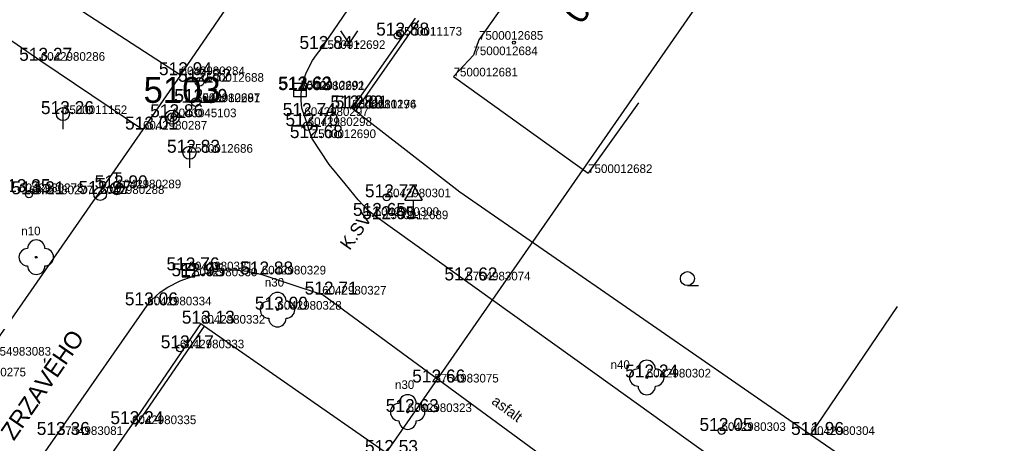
# Model space of a CAD drawing. Extents: x -669251 to -668549, y -1128351 to -1127698.
# Drawn here: x -668939.6 to -668883.4, y -1128097.2 to -1128072.7 of the extents above; entities that cross this region are included whole.
import ezdxf

# ---------------------------------------------------------------- set-up
doc = ezdxf.new("R2010")
doc.units = 0
for name, color, linetype in [('Vrstva 1', 7, 'Continuous'), ('Vrstva 10', 7, 'Continuous'), ('Vrstva 2', 7, 'Continuous'), ('Vrstva 22', 7, 'Continuous'), ('Vrstva 25', 7, 'Continuous'), ('Vrstva 27', 7, 'Continuous'), ('Vrstva 28', 7, 'Continuous'), ('Vrstva 3', 7, 'Continuous'), ('Vrstva 34', 7, 'Continuous'), ('Vrstva 36', 7, 'Continuous'), ('Vrstva 40', 7, 'Continuous'), ('Vrstva 42', 7, 'Continuous'), ('Vrstva 44', 7, 'Continuous'), ('Vrstva 45', 7, 'Continuous'), ('Vrstva 47', 7, 'Continuous'), ('Vrstva 5', 7, 'Continuous'), ('Vrstva 58', 7, 'Continuous'), ('Vrstva 6', 7, 'Continuous'), ('Vrstva 60', 7, 'Continuous'), ('Vrstva 63', 7, 'Continuous'), ('Vrstva 7', 7, 'Continuous'), ('Vrstva 8', 7, 'Continuous')]:
    doc.layers.add(name, color=color, linetype=linetype)

msp = doc.modelspace()

# ---------------------------------------------------------------- linework, layer by layer
at = {"layer": 'Vrstva 1'}
for p, q in [((-668917.686, -1128073.591), (-668917.686, -1128073.591)), ((-668922.122, -1128074.364), (-668922.122, -1128074.364)), ((-668912.989, -1128073.832), (-668912.989, -1128073.832)), ((-668913.309, -1128074.724), (-668913.309, -1128074.724)), ((-668938.339, -1128075.049), (-668938.339, -1128075.049)), ((-668930.251, -1128075.881), (-668930.251, -1128075.881)), ((-668914.458, -1128075.953), (-668914.458, -1128075.953)), ((-668929.15, -1128076.263), (-668929.15, -1128076.263)), ((-668923.347, -1128076.747), (-668923.347, -1128076.747)), ((-668923.31, -1128076.708), (-668923.31, -1128076.708)), ((-668929.366, -1128077.444), (-668929.366, -1128077.444)), ((-668929.36, -1128077.427), (-668929.36, -1128077.427)), ((-668937.059, -1128078.133), (-668937.059, -1128078.133)), ((-668923.09, -1128078.24), (-668923.09, -1128078.24)), ((-668920.329, -1128077.805), (-668920.329, -1128077.805)), ((-668920.315, -1128077.808), (-668920.315, -1128077.808)), ((-668930.737, -1128078.313), (-668930.737, -1128078.313)), ((-668922.897, -1128078.823), (-668922.897, -1128078.823)), ((-668932.431, -1128079.028), (-668932.431, -1128079.028)), ((-668922.664, -1128079.521), (-668922.664, -1128079.521)), ((-668929.788, -1128080.369), (-668929.788, -1128080.369)), ((-668906.673, -1128081.541), (-668906.673, -1128081.541)), ((-668939.025, -1128082.769), (-668939.025, -1128082.769)), ((-668934.906, -1128082.752), (-668934.906, -1128082.752)), ((-668933.936, -1128082.425), (-668933.936, -1128082.425)), ((-668918.335, -1128082.945), (-668918.335, -1128082.945)), ((-668919.017, -1128084.023), (-668919.017, -1128084.023)), ((-668918.483, -1128084.212), (-668918.483, -1128084.212)), ((-668929.795, -1128087.171), (-668929.795, -1128087.171)), ((-668929.527, -1128087.514), (-668929.527, -1128087.514)), ((-668925.555, -1128087.41), (-668925.555, -1128087.41)), ((-668913.722, -1128087.754), (-668913.722, -1128087.754)), ((-668922.059, -1128088.573), (-668922.059, -1128088.573)), ((-668932.181, -1128089.197), (-668932.181, -1128089.197)), ((-668924.648, -1128089.447), (-668924.648, -1128089.447)), ((-668929.072, -1128090.256), (-668929.072, -1128090.256)), ((-668930.29, -1128091.683), (-668930.29, -1128091.683)), ((-668903.282, -1128093.37), (-668903.282, -1128093.37)), ((-668915.564, -1128093.66), (-668915.564, -1128093.66)), ((-668917.116, -1128095.37), (-668917.116, -1128095.37)), ((-668933.061, -1128096.069), (-668933.061, -1128096.069)), ((-668937.301, -1128096.694), (-668937.301, -1128096.694)), ((-668898.955, -1128096.464), (-668898.955, -1128096.464)), ((-668893.8, -1128096.695), (-668893.8, -1128096.695))]:
    msp.add_line(p, q, dxfattribs=at)
at = {"layer": 'Vrstva 10'}
for p, q in [((-668930.251, -1128075.881), (-668923.264, -1128065.653)), ((-668945.235, -1128070.371), (-668938.339, -1128075.049)), ((-668930.251, -1128075.881), (-668936.233, -1128072.009)), ((-668938.339, -1128075.049), (-668932.431, -1128079.028)), ((-668930.251, -1128075.881), (-668932.431, -1128079.028)), ((-668932.431, -1128079.028), (-668946.986, -1128099.95)), ((-668899.916, -1128104.805), (-668922.059, -1128088.573))]:
    msp.add_line(p, q, dxfattribs=at)
for points in [[(-668891.508, -1128103.738), (-668905.262, -1128093.88), (-668919.017, -1128084.023), (-668919.397, -1128083.714), (-668919.979, -1128083.09), (-668920.732, -1128082.168), (-668921.655, -1128081.051), (-668922.664, -1128079.521), (-668923.09, -1128078.24), (-668923.232, -1128077.783), (-668923.284, -1128077.351), (-668923.278, -1128076.957), (-668923.161, -1128076.255), (-668922.993, -1128075.739), (-668922.626, -1128075.026), (-668922.397, -1128074.711), (-668922.122, -1128074.364), (-668919.566, -1128070.623)], [(-668949.552, -1128114.045), (-668940.866, -1128101.621), (-668932.181, -1128089.197), (-668931.937, -1128088.891), (-668931.427, -1128088.43), (-668930.99, -1128088.14), (-668930.277, -1128087.786), (-668929.527, -1128087.514), (-668928.538, -1128087.269), (-668927.781, -1128087.169), (-668927.212, -1128087.149), (-668926.37, -1128087.215), (-668925.555, -1128087.41), (-668923.807, -1128087.992), (-668922.059, -1128088.573)]]:
    msp.add_lwpolyline(points, dxfattribs=at)
at = {"layer": 'Vrstva 22'}
for centre in [(-668938.603, -1128086.412), (-668924.648, -1128089.447), (-668903.282, -1128093.37), (-668917.116, -1128095.37)]:
    msp.add_circle(centre, 0.05, dxfattribs=at)
for centre, start, end in [((-668938.603, -1128085.912), 0, 180), ((-668939.103, -1128086.412), 90, 270), ((-668938.103, -1128086.412), 270, 90), ((-668938.603, -1128086.912), 180, 0), ((-668925.148, -1128089.447), 90, 270), ((-668924.648, -1128088.947), 0, 180), ((-668924.148, -1128089.447), 270, 90), ((-668924.648, -1128089.947), 180, 0), ((-668903.782, -1128093.37), 90, 270), ((-668903.282, -1128092.87), 0, 180), ((-668902.782, -1128093.37), 270, 90), ((-668903.282, -1128093.87), 180, 0), ((-668917.116, -1128094.87), 0, 180), ((-668917.616, -1128095.37), 90, 270), ((-668916.616, -1128095.37), 270, 90), ((-668917.116, -1128095.87), 180, 0)]:
    msp.add_arc(centre, 0.5, start, end, dxfattribs=at)
at = {"layer": 'Vrstva 25'}
for centre in [(-668917.686, -1128073.591), (-668917.562, -1128073.461), (-668939.025, -1128082.769), (-668918.335, -1128082.945), (-668930.29, -1128091.683), (-668898.955, -1128096.464)]:
    msp.add_circle(centre, 0.2, dxfattribs=at)
at = {"layer": 'Vrstva 27'}
for p, q in [((-668923.722, -1128076.747), (-668922.972, -1128076.747)), ((-668937.059, -1128077.758), (-668937.059, -1128079.008)), ((-668929.738, -1128079.996), (-668929.738, -1128081.246)), ((-668930.17, -1128087.171), (-668929.42, -1128087.171))]:
    msp.add_line(p, q, dxfattribs=at)
for points in [[(-668923.722, -1128077.121), (-668922.972, -1128077.121), (-668922.972, -1128076.371), (-668923.722, -1128076.371)], [(-668930.17, -1128087.545), (-668929.42, -1128087.545), (-668929.42, -1128086.795), (-668930.17, -1128086.795)]]:
    msp.add_lwpolyline(points, close=True, dxfattribs=at)
for centre in [(-668937.059, -1128078.133), (-668929.738, -1128080.371)]:
    msp.add_circle(centre, 0.375, dxfattribs=at)
at = {"layer": 'Vrstva 28'}
for p, q in [((-668929.4, -1128076.263), (-668929.9, -1128076.263)), ((-668928.9, -1128076.263), (-668928.4, -1128076.263)), ((-668929.616, -1128077.444), (-668930.116, -1128077.444)), ((-668929.116, -1128077.444), (-668928.616, -1128077.444)), ((-668930.99, -1128078.31), (-668931.49, -1128078.31)), ((-668930.49, -1128078.31), (-668929.99, -1128078.31)), ((-668923.147, -1128078.823), (-668923.647, -1128078.823)), ((-668922.647, -1128078.823), (-668922.147, -1128078.823)), ((-668934.186, -1128081.525), (-668933.686, -1128081.525)), ((-668933.936, -1128082.05), (-668933.936, -1128081.525)), ((-668935.156, -1128081.852), (-668934.656, -1128081.852)), ((-668934.906, -1128082.377), (-668934.906, -1128081.852)), ((-668934.201, -1128082.69), (-668933.671, -1128082.16)), ((-668935.171, -1128083.017), (-668934.641, -1128082.487))]:
    msp.add_line(p, q, dxfattribs=at)
for centre, radius in [((-668929.15, -1128076.263), 0.25), ((-668929.366, -1128077.444), 0.25), ((-668930.74, -1128078.31), 0.25), ((-668922.897, -1128078.823), 0.25), ((-668933.936, -1128082.425), 0.375), ((-668934.906, -1128082.752), 0.375)]:
    msp.add_circle(centre, radius, dxfattribs=at)
at = {"layer": 'Vrstva 34'}
for p, q in [((-668917.272, -1128083.111), (-668916.772, -1128082.261)), ((-668916.772, -1128082.261), (-668916.272, -1128083.111)), ((-668917.272, -1128083.111), (-668916.272, -1128083.111)), ((-668916.772, -1128084.111), (-668916.772, -1128083.111)), ((-668917.022, -1128084.111), (-668916.522, -1128084.111))]:
    msp.add_line(p, q, dxfattribs=at)
at = {"layer": 'Vrstva 36'}
for p, q in [((-668921, -1128073.316), (-668920.5, -1128074.066)), ((-668920.5, -1128074.066), (-668920, -1128073.316)), ((-668900.93, -1128088.054), (-668900.28, -1128088.051))]:
    msp.add_line(p, q, dxfattribs=at)
for centre, radius in [((-668920.999, -1128074.066), 0.05), ((-668919.999, -1128074.066), 0.05), ((-668900.93, -1128087.651), 0.403)]:
    msp.add_circle(centre, radius, dxfattribs=at)
at = {"layer": 'Vrstva 5'}
for p, q in [((-668909.282, -1128068.562), (-668912.989, -1128073.832)), ((-668913.309, -1128074.724), (-668914.458, -1128075.953)), ((-668914.458, -1128075.953), (-668906.673, -1128081.541)), ((-668903.757, -1128077.479), (-668906.673, -1128081.541))]:
    msp.add_line(p, q, dxfattribs=at)
at = {"layer": 'Vrstva 58'}
msp.add_circle((-668910.969, -1128073.999), 0.0875, dxfattribs=at)
at = {"layer": 'Vrstva 6'}
msp.add_line((-668912.989, -1128073.832), (-668913.309, -1128074.724), dxfattribs=at)
at = {"layer": 'Vrstva 60'}
msp.add_lwpolyline([(-668982.815, -1128190.464), (-668751.689, -1127857.889), (-668981.618, -1127698.099), (-669212.743, -1128030.674)], close=True, dxfattribs=at)
at = {"layer": 'Vrstva 63'}
for radius in [0.412, 0.412, 0.05, 0.05]:
    msp.add_circle((-668930.737, -1128078.313), radius, dxfattribs=at)
at = {"layer": 'Vrstva 7'}
for p, q in [((-668920.329, -1128077.805), (-668916.667, -1128072.578)), ((-668920.131, -1128077.959), (-668916.462, -1128072.721)), ((-668920.131, -1128077.959), (-668920.329, -1128077.805)), ((-668914.088, -1128082.656), (-668920.131, -1128077.959)), ((-668893.8, -1128096.695), (-668914.088, -1128082.656)), ((-668893.8, -1128096.695), (-668888.769, -1128089.258)), ((-668929.072, -1128090.256), (-668933.061, -1128096.069)), ((-668932.854, -1128096.21), (-668928.865, -1128090.397)), ((-668929.072, -1128090.256), (-668928.865, -1128090.397)), ((-668928.865, -1128090.397), (-668918.333, -1128097.737)), ((-668871.366, -1128112.099), (-668893.8, -1128096.695))]:
    msp.add_line(p, q, dxfattribs=at)
at = {"layer": 'Vrstva 8'}
msp.add_line((-668933.061, -1128096.069), (-668934.967, -1128098.819), dxfattribs=at)

# ---------------------------------------------------------------- texts
at = {"layer": 'Vrstva 2'}
for s, p in [('7500011173', (-668917.686, -1128073.591)), ('7500012685', (-668912.989, -1128073.832)), ('7500012692', (-668922.122, -1128074.364)), ('7500012684', (-668913.309, -1128074.724)), ('6042980286', (-668938.339, -1128075.049)), ('6042980284', (-668930.251, -1128075.881)), ('7500012681', (-668914.458, -1128075.953)), ('7500012688', (-668929.15, -1128076.263)), ('6042980292', (-668923.347, -1128076.747)), ('7500012691', (-668923.31, -1128076.708)), ('6042980291', (-668929.366, -1128077.444)), ('7500012687', (-668929.36, -1128077.427)), ('7500011152', (-668937.059, -1128078.133)), ('6042980297', (-668923.09, -1128078.24)), ('6042980296', (-668920.329, -1128077.805)), ('7500011174', (-668920.315, -1128077.808)), ('6043045103', (-668930.737, -1128078.313)), ('6042980287', (-668932.431, -1128079.028)), ('6042980298', (-668922.897, -1128078.823)), ('7500012690', (-668922.664, -1128079.521)), ('7500012686', (-668929.788, -1128080.369)), ('7500012682', (-668906.673, -1128081.541)), ('6042980278', (-668939.595, -1128082.647)), ('6042980289', (-668933.936, -1128082.425)), ('6042980277', (-668939.025, -1128082.769)), ('6042980288', (-668934.906, -1128082.752)), ('6042980301', (-668918.335, -1128082.945)), ('6042980300', (-668919.017, -1128084.023)), ('7500012689', (-668918.483, -1128084.212)), ('6042980331', (-668929.795, -1128087.171)), ('6042980330', (-668929.527, -1128087.514)), ('6042980329', (-668925.555, -1128087.41)), ('5754983074', (-668913.722, -1128087.754)), ('6042980327', (-668922.059, -1128088.573)), ('6042980334', (-668932.181, -1128089.197)), ('6042980328', (-668924.648, -1128089.447)), ('6042980332', (-668929.072, -1128090.256)), ('6042980333', (-668930.29, -1128091.683)), ('5754983083', (-668941.468, -1128092.105)), ('6042980275', (-668942.914, -1128093.308)), ('6042980302', (-668903.282, -1128093.37)), ('5754983075', (-668915.564, -1128093.66)), ('6042980323', (-668917.116, -1128095.37)), ('6042980335', (-668933.061, -1128096.069)), ('5754983081', (-668937.301, -1128096.694)), ('6042980303', (-668898.955, -1128096.464)), ('6042980304', (-668893.8, -1128096.695))]:
    msp.add_text(s, height=0.5, dxfattribs=at).set_placement(p)
at = {"layer": 'Vrstva 3'}
for s, p in [('512.88 ', (-668918.938, -1128073.591)), ('512.84 ', (-668923.374, -1128074.364)), ('513.27 ', (-668939.591, -1128075.049)), ('512.94 ', (-668931.505, -1128075.881)), ('512.82 ', (-668930.402, -1128076.263)), ('512.63 ', (-668924.613, -1128076.747)), ('512.62 ', (-668924.576, -1128076.708)), ('512.79 ', (-668930.621, -1128077.444)), ('512.79 ', (-668930.615, -1128077.427)), ('512.89 ', (-668921.584, -1128077.805)), ('512.91 ', (-668921.332, -1128077.808)), ('513.26 ', (-668938.333, -1128078.133)), ('512.86 ', (-668932.011, -1128078.313)), ('512.74 ', (-668924.342, -1128078.24)), ('513.01 ', (-668933.468, -1128079.028)), ('512.70 ', (-668924.185, -1128078.823)), ('512.68 ', (-668923.93, -1128079.521)), ('512.83 ', (-668931.04, -1128080.369)), ('512.90 ', (-668935.226, -1128082.425)), ('513.35 ', (-668940.847, -1128082.647)), ('513.31 ', (-668940.04, -1128082.769)), ('512.97 ', (-668936.16, -1128082.752)), ('512.77 ', (-668919.587, -1128082.945)), ('512.65 ', (-668920.283, -1128084.023)), ('512.65 ', (-668919.749, -1128084.212)), ('512.76 ', (-668931.069, -1128087.171)), ('512.88 ', (-668926.807, -1128087.41)), ('512.95 ', (-668930.781, -1128087.514)), ('512.62 ', (-668914.988, -1128087.754)), ('512.71 ', (-668923.074, -1128088.573)), ('513.06 ', (-668933.477, -1128089.197)), ('513.00 ', (-668925.957, -1128089.447)), ('513.13 ', (-668930.182, -1128090.256)), ('513.17 ', (-668931.4, -1128091.683)), ('512.66 ', (-668916.852, -1128093.66)), ('512.24 ', (-668904.534, -1128093.37)), ('512.63 ', (-668918.382, -1128095.37)), ('513.24 ', (-668934.313, -1128096.069)), ('512.05 ', (-668900.229, -1128096.464)), ('513.36 ', (-668938.575, -1128096.694)), ('511.96 ', (-668894.935, -1128096.695)), ('512.53 ', (-668919.585, -1128097.737))]:
    msp.add_text(s, height=0.75, dxfattribs=at).set_placement(p)
at = {"layer": 'Vrstva 40'}
msp.add_text('asfalt', height=0.6, rotation=323.7566, dxfattribs=at).set_placement((-668912.308, -1128094.853))
at = {"layer": 'Vrstva 42'}
msp.add_text('K.SV.', height=0.75, rotation=54.686, dxfattribs=at).set_placement((-668920.475, -1128086.053))
at = {"layer": 'Vrstva 44'}
msp.add_text('20', height=1.5, rotation=234.5334, dxfattribs=at).set_placement((-668907.001, -1128070.338))
at = {"layer": 'Vrstva 45'}
msp.add_text('ZRZAVÉHO', height=1, rotation=55.5352, dxfattribs=at).set_placement((-668939.9, -1128097.074))
at = {"layer": 'Vrstva 47'}
for s, height, p in [('n10', 0.5, (-668939.471, -1128085.142)), ('n30', 0.499, (-668925.378, -1128088.111)), ('n40', 0.499, (-668905.376, -1128092.873)), ('n30', 0.499, (-668917.846, -1128094.034))]:
    msp.add_text(s, height=height, dxfattribs=at).set_placement(p)
at = {"layer": 'Vrstva 63'}
msp.add_text('5103', height=1.5, dxfattribs=at).set_placement((-668932.395, -1128077.483))
msp.add_text('5103', height=1.5, dxfattribs=at).set_placement((-668932.395, -1128077.483))

doc.saveas('drawing.dxf')
